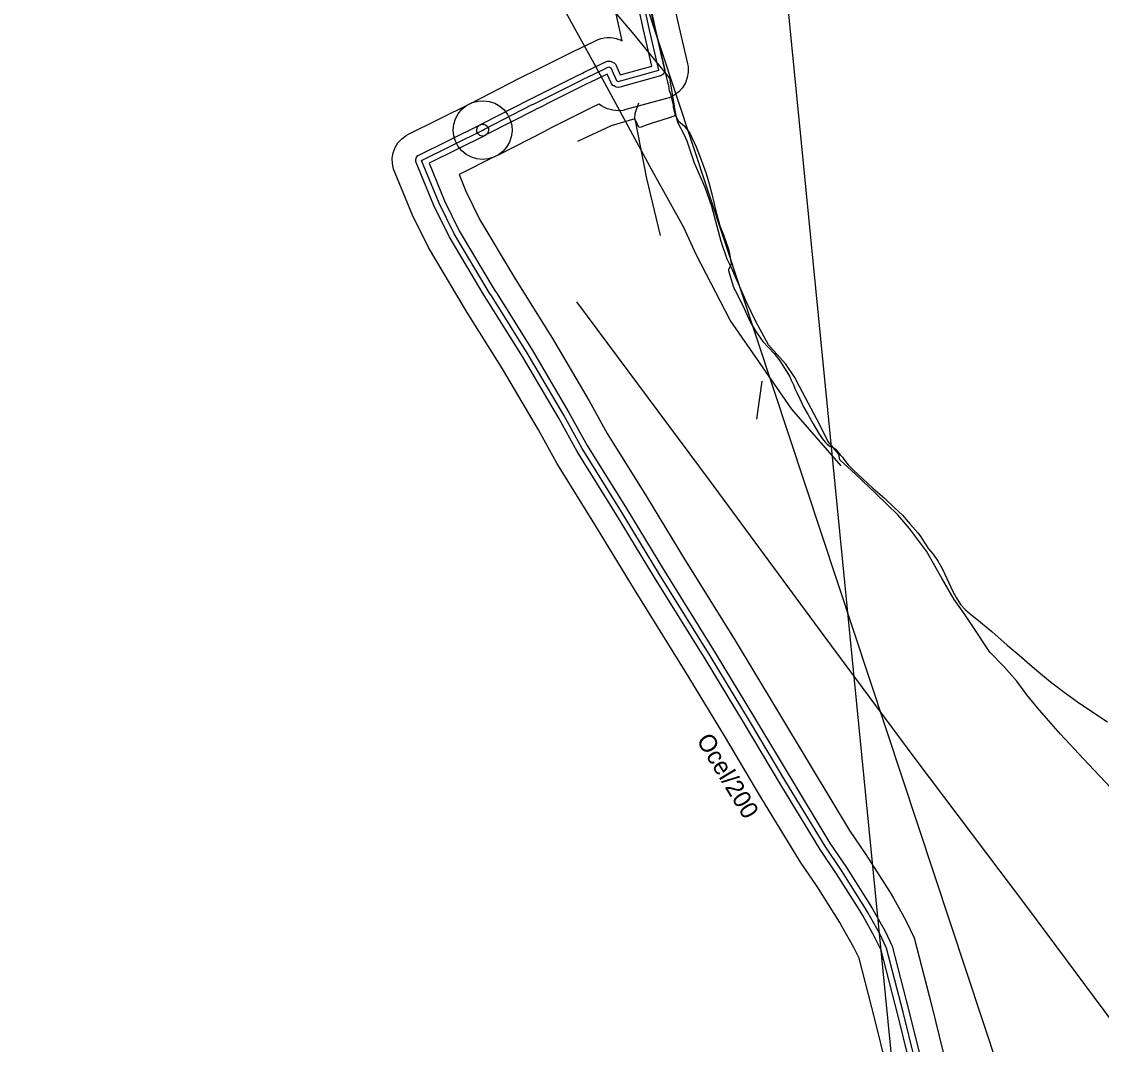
# Model space of a CAD drawing. Extents: x -555222 to -543220, y -1067119 to -1030889.
# Drawn here: x -550559 to -549821, y -1046964 to -1046265 of the extents above; entities that cross this region are included whole.
import ezdxf

# ---------------------------------------------------------------- set-up
doc = ezdxf.new("R2010")
doc.units = 0
for name, color, linetype in [('07_ELEKTRO', 7, 'Continuous'), ('07_KANALIZACE', 7, 'Continuous'), ('07_OCH_P A POPISY TI', 7, 'Continuous'), ('07_PLYNOVOD', 7, 'Continuous'), ('07_SDĚLOVACÍ', 7, 'Continuous')]:
    doc.layers.add(name, color=color, linetype=linetype)

msp = doc.modelspace()

# ---------------------------------------------------------------- linework, layer by layer
at = {"layer": '07_ELEKTRO'}
for p, q in [((-550088.84, -1046578.41), (-550179.46, -1046456.56)), ((-550053.06, -1046510.77), (-550056.73, -1046536.66)), ((-550010.41, -1046684.72), (-550088.84, -1046578.41)), ((-549948.06, -1046768.56), (-550010.41, -1046684.72)), ((-549871.17, -1046870.7), (-549948.06, -1046768.56)), ((-549805.69, -1046958.54), (-549871.17, -1046870.7))]:
    msp.add_line(p, q, dxfattribs=at)
at = {"layer": '07_KANALIZACE'}
msp.add_lwpolyline([(-549998.78, -1046568.66), (-550032.5, -1046529.85), (-550074.63, -1046469.01), (-550097.74, -1046424.54), (-550106.48, -1046405.31), (-550126.67, -1046369.27), (-550167.68, -1046293.63), (-550196.35, -1046241.61)], dxfattribs=at)
at = {"layer": '07_OCH_P A POPISY TI'}
for p, q in [((-550119.87, -1046221.9), (-550110.42, -1046265.31)), ((-550149.46, -1046274.05), (-550158.95, -1046230.46)), ((-550133.84, -1046270.55), (-550143.32, -1046227.04)), ((-550135.5, -1046225.32), (-550126.04, -1046268.81)), ((-550110.42, -1046265.31), (-550104.34, -1046291.76)), ((-550148.53, -1046278.08), (-550149.46, -1046274.05)), ((-550128.12, -1046295.44), (-550133.84, -1046270.55)), ((-550126.04, -1046268.81), (-550119.93, -1046295.34)), ((-550181.46, -1046285.24), (-550168.56, -1046279.02)), ((-550168.56, -1046279.02), (-550168.04, -1046278.78)), ((-550168.04, -1046278.78), (-550167.63, -1046278.58)), ((-550167.63, -1046278.58), (-550165.79, -1046277.75)), ((-550165.79, -1046277.75), (-550164.85, -1046277.32)), ((-550164.85, -1046277.32), (-550162.88, -1046276.67)), ((-550162.88, -1046276.67), (-550160.86, -1046276.22)), ((-550160.86, -1046276.22), (-550158.8, -1046275.98)), ((-550158.8, -1046275.98), (-550156.72, -1046275.96)), ((-550156.72, -1046275.96), (-550154.66, -1046276.15)), ((-550154.66, -1046276.15), (-550152.62, -1046276.56)), ((-550152.62, -1046276.56), (-550150.64, -1046277.17)), ((-550150.64, -1046277.17), (-550149.69, -1046277.58)), ((-550149.69, -1046277.58), (-550148.53, -1046278.08)), ((-550207.45, -1046298.22), (-550186.93, -1046287.96)), ((-550186.93, -1046287.96), (-550182.74, -1046285.88)), ((-550182.74, -1046285.88), (-550181.46, -1046285.24)), ((-550174.42, -1046299.61), (-550161.61, -1046293.43)), ((-550161.61, -1046293.43), (-550161.14, -1046293.21)), ((-550161.14, -1046293.21), (-550160.91, -1046293.1)), ((-550160.91, -1046293.1), (-550159.2, -1046292.33)), ((-550159.2, -1046292.33), (-550158.43, -1046291.98)), ((-550158.43, -1046291.98), (-550156.75, -1046291.96)), ((-550156.75, -1046291.96), (-550155.98, -1046292.29)), ((-550155.98, -1046292.29), (-550154.6, -1046292.88)), ((-550154.6, -1046292.88), (-550153.89, -1046293.18)), ((-550153.89, -1046293.18), (-550152.8, -1046294.27)), ((-550152.8, -1046294.27), (-550152.5, -1046294.98)), ((-550152.5, -1046294.98), (-550149.74, -1046301.36)), ((-550149.74, -1046301.36), (-550128.12, -1046295.44)), ((-550119.93, -1046295.34), (-550119.46, -1046297.4)), ((-550119.46, -1046297.4), (-550119.29, -1046298.15)), ((-550104.34, -1046291.76), (-550103.87, -1046293.82)), ((-550103.87, -1046293.82), (-550103.44, -1046295.69)), ((-550103.44, -1046295.69), (-550103.31, -1046299.52)), ((-550251.73, -1046320.74), (-550218.98, -1046303.99)), ((-550218.98, -1046303.99), (-550218.56, -1046303.77)), ((-550218.56, -1046303.77), (-550213.97, -1046301.48)), ((-550213.97, -1046301.48), (-550210.25, -1046299.62)), ((-550210.25, -1046299.62), (-550207.45, -1046298.22)), ((-550200.3, -1046312.53), (-550179.79, -1046302.28)), ((-550179.79, -1046302.28), (-550175.61, -1046300.2)), ((-550175.61, -1046300.2), (-550174.42, -1046299.61)), ((-550158.66, -1046300.89), (-550170.9, -1046306.79)), ((-550156.06, -1046306.91), (-550158.66, -1046300.89)), ((-550122.3, -1046302.15), (-550150.14, -1046309.77)), ((-550121.56, -1046301.94), (-550122.3, -1046302.15)), ((-550120.32, -1046301.01), (-550121.56, -1046301.94)), ((-550119.53, -1046299.68), (-550120.32, -1046301.01)), ((-550119.29, -1046298.15), (-550119.53, -1046299.68)), ((-550103.9, -1046303.31), (-550105.21, -1046306.91)), ((-550103.31, -1046299.52), (-550103.9, -1046303.31)), ((-550176.21, -1046309.44), (-550196.72, -1046319.69)), ((-550172.04, -1046307.36), (-550176.21, -1046309.44)), ((-550170.9, -1046306.79), (-550172.04, -1046307.36)), ((-550155.78, -1046307.58), (-550156.06, -1046306.91)), ((-550154.77, -1046308.63), (-550155.78, -1046307.58)), ((-550154.11, -1046308.94), (-550154.77, -1046308.63)), ((-550153.92, -1046309.03), (-550154.11, -1046308.94)), ((-550152.96, -1046309.5), (-550153.92, -1046309.03)), ((-550152.3, -1046309.82), (-550152.96, -1046309.5)), ((-550150.85, -1046309.96), (-550152.3, -1046309.82)), ((-550150.14, -1046309.77), (-550150.85, -1046309.96)), ((-550107.18, -1046310.2), (-550109.74, -1046313.06)), ((-550105.21, -1046306.91), (-550107.18, -1046310.2)), ((-550250.9, -1046320.37), (-550247.1, -1046319.35)), ((-550247.1, -1046319.35), (-550243.16, -1046319.08)), ((-550244.34, -1046334.93), (-550211.68, -1046318.22)), ((-550243.16, -1046319.08), (-550239.26, -1046319.59)), ((-550239.26, -1046319.59), (-550235.52, -1046320.85)), ((-550211.68, -1046318.22), (-550211.33, -1046318.04)), ((-550211.33, -1046318.04), (-550206.82, -1046315.79)), ((-550206.82, -1046315.79), (-550203.1, -1046313.93)), ((-550203.1, -1046313.93), (-550200.3, -1046312.53)), ((-550118.08, -1046317.58), (-550145.92, -1046325.2)), ((-550116.23, -1046317.07), (-550118.08, -1046317.58)), ((-550112.79, -1046315.38), (-550116.23, -1046317.07)), ((-550109.74, -1046313.06), (-550112.79, -1046315.38)), ((-550294.45, -1046341.94), (-550252.66, -1046321.25)), ((-550260.47, -1046327.96), (-550257.96, -1046324.92)), ((-550257.96, -1046324.92), (-550254.91, -1046322.43)), ((-550254.91, -1046322.43), (-550253.17, -1046321.5)), ((-550253.17, -1046321.5), (-550251.73, -1046320.74)), ((-550252.66, -1046321.25), (-550250.9, -1046320.37)), ((-550208.02, -1046325.34), (-550240.64, -1046342.03)), ((-550235.52, -1046320.85), (-550232.11, -1046322.82)), ((-550232.11, -1046322.82), (-550229.14, -1046325.41)), ((-550229.14, -1046325.41), (-550226.74, -1046328.53)), ((-550207.71, -1046325.18), (-550208.02, -1046325.34)), ((-550203.24, -1046322.95), (-550207.71, -1046325.18)), ((-550199.52, -1046321.09), (-550203.24, -1046322.95)), ((-550196.72, -1046319.69), (-550199.52, -1046321.09)), ((-550169.07, -1046323.76), (-550189.57, -1046334)), ((-550164.91, -1046321.68), (-550169.07, -1046323.76)), ((-550164.32, -1046321.39), (-550164.91, -1046321.68)), ((-550162.62, -1046322.61), (-550164.32, -1046321.39)), ((-550160.99, -1046323.39), (-550162.62, -1046322.61)), ((-550160.88, -1046323.44), (-550160.99, -1046323.39)), ((-550160, -1046323.87), (-550160.88, -1046323.44)), ((-550158.37, -1046324.67), (-550160, -1046323.87)), ((-550154.88, -1046325.65), (-550158.37, -1046324.67)), ((-550151.28, -1046325.99), (-550154.88, -1046325.65)), ((-550147.67, -1046325.68), (-550151.28, -1046325.99)), ((-550145.92, -1046325.2), (-550147.67, -1046325.68)), ((-550263.49, -1046335.19), (-550262.33, -1046331.42)), ((-550262.33, -1046331.42), (-550260.47, -1046327.96)), ((-550226.74, -1046328.53), (-550225.87, -1046330.3)), ((-550225.87, -1046330.3), (-550224.99, -1046332.06)), ((-550224.99, -1046332.06), (-550223.97, -1046335.86)), ((-550189.57, -1046334), (-550192.37, -1046335.4)), ((-550287.36, -1046356.28), (-550245.56, -1046335.58)), ((-550263.89, -1046339.11), (-550263.49, -1046335.19)), ((-550263.51, -1046343.03), (-550263.89, -1046339.11)), ((-550247.85, -1046338.76), (-550247.38, -1046337.24)), ((-550247.7, -1046340.34), (-550247.85, -1046338.76)), ((-550247.32, -1046341.04), (-550247.7, -1046340.34)), ((-550247.38, -1046337.24), (-550246.37, -1046336.01)), ((-550246.95, -1046341.75), (-550247.32, -1046341.04)), ((-550246.37, -1046336.01), (-550245.66, -1046335.64)), ((-550245.66, -1046335.64), (-550244.34, -1046334.93)), ((-550245.56, -1046335.58), (-550244.85, -1046335.23)), ((-550244.85, -1046335.23), (-550243.26, -1046335.13)), ((-550243.26, -1046335.13), (-550241.76, -1046335.64)), ((-550241.76, -1046335.64), (-550240.56, -1046336.68)), ((-550240.26, -1046341.2), (-550241.3, -1046342.4)), ((-550240.56, -1046336.68), (-550240.2, -1046337.4)), ((-550239.75, -1046339.7), (-550240.26, -1046341.2)), ((-550240.2, -1046337.4), (-550239.85, -1046338.11)), ((-550239.85, -1046338.11), (-550239.75, -1046339.7)), ((-550200.72, -1046339.57), (-550233.25, -1046356.22)), ((-550223.7, -1046339.8), (-550224.21, -1046343.7)), ((-550223.97, -1046335.86), (-550223.7, -1046339.8)), ((-550200.48, -1046339.45), (-550200.72, -1046339.57)), ((-550196.09, -1046337.26), (-550200.48, -1046339.45)), ((-550192.37, -1046335.4), (-550196.09, -1046337.26)), ((-550303.65, -1046351.08), (-550301.68, -1046347.85)), ((-550301.68, -1046347.85), (-550299.15, -1046345.05)), ((-550299.15, -1046345.05), (-550296.14, -1046342.77)), ((-550296.14, -1046342.77), (-550294.45, -1046341.94)), ((-550242.02, -1046342.76), (-550280.45, -1046361.78)), ((-550262.38, -1046346.81), (-550263.51, -1046343.03)), ((-550261.46, -1046348.55), (-550262.38, -1046346.81)), ((-550260.53, -1046350.29), (-550261.46, -1046348.55)), ((-550245.72, -1046342.76), (-550246.95, -1046341.75)), ((-550244.2, -1046343.23), (-550245.72, -1046342.76)), ((-550242.62, -1046343.08), (-550244.2, -1046343.23)), ((-550241.92, -1046342.7), (-550242.62, -1046343.08)), ((-550241.3, -1046342.4), (-550242.02, -1046342.76)), ((-550240.64, -1046342.03), (-550241.92, -1046342.7)), ((-550225.47, -1046347.44), (-550227.44, -1046350.85)), ((-550224.21, -1046343.7), (-550225.47, -1046347.44)), ((-550305.61, -1046358.33), (-550304.97, -1046354.61)), ((-550304.97, -1046354.61), (-550303.65, -1046351.08)), ((-550288.04, -1046356.61), (-550287.36, -1046356.28)), ((-550258.04, -1046353.34), (-550260.53, -1046350.29)), ((-550255, -1046355.85), (-550258.04, -1046353.34)), ((-550251.54, -1046357.71), (-550255, -1046355.85)), ((-550233.15, -1046356.22), (-550234.92, -1046357.09)), ((-550233.25, -1046356.22), (-550234.41, -1046356.84)), ((-550230.03, -1046353.82), (-550233.15, -1046356.22)), ((-550227.44, -1046350.85), (-550230.03, -1046353.82)), ((-550305.54, -1046362.1), (-550305.61, -1046358.33)), ((-550304.77, -1046365.8), (-550305.54, -1046362.1)), ((-550289.59, -1046359.17), (-550289.06, -1046357.74)), ((-550289.57, -1046360.69), (-550289.59, -1046359.17)), ((-550289.27, -1046361.4), (-550289.57, -1046360.69)), ((-550277.08, -1046390.72), (-550289.27, -1046361.4)), ((-550289.06, -1046357.74), (-550288.04, -1046356.61)), ((-550280.45, -1046361.78), (-550269.78, -1046387.44)), ((-550234.92, -1046357.09), (-550259.92, -1046369.47)), ((-550247.77, -1046358.87), (-550251.54, -1046357.71)), ((-550243.85, -1046359.27), (-550247.77, -1046358.87)), ((-550239.93, -1046358.89), (-550243.85, -1046359.27)), ((-550236.15, -1046357.76), (-550239.93, -1046358.89)), ((-550234.41, -1046356.84), (-550236.15, -1046357.76)), ((-550304.05, -1046367.54), (-550304.77, -1046365.8)), ((-550291.67, -1046397.3), (-550304.05, -1046367.54)), ((-550259.92, -1046369.47), (-550255.19, -1046380.86)), ((-550255.19, -1046380.86), (-550245.66, -1046400.44)), ((-550266.79, -1046411.86), (-550277.08, -1046390.72)), ((-550269.78, -1046387.44), (-550259.75, -1046408.06)), ((-550280.88, -1046419.48), (-550291.67, -1046397.3)), ((-550245.66, -1046400.44), (-550222.21, -1046439.7)), ((-550259.75, -1046408.06), (-550235.88, -1046448.01)), ((-550242.72, -1046452.17), (-550266.79, -1046411.86)), ((-550256.39, -1046460.48), (-550280.88, -1046419.48)), ((-550222.21, -1046439.7), (-550220.4, -1046442.63)), ((-550220.4, -1046442.63), (-550196.11, -1046481.53)), ((-550240.79, -1046455.29), (-550242.72, -1046452.17)), ((-550235.88, -1046448.01), (-550233.99, -1046451.07)), ((-550233.99, -1046451.07), (-550209.79, -1046489.84)), ((-550216.63, -1046493.98), (-550240.79, -1046455.29)), ((-550254.38, -1046463.73), (-550256.39, -1046460.48)), ((-550230.31, -1046502.29), (-550254.38, -1046463.73)), ((-550196.11, -1046481.53), (-550170.98, -1046524.17)), ((-550191.82, -1046536.06), (-550216.63, -1046493.98)), ((-550209.79, -1046489.84), (-550184.88, -1046532.1)), ((-550205.72, -1046543.99), (-550230.31, -1046502.29)), ((-550170.98, -1046524.17), (-550158.6, -1046546.62)), ((-550184.88, -1046532.1), (-550172.4, -1046554.72)), ((-550179.3, -1046558.78), (-550191.82, -1046536.06)), ((-550193.1, -1046566.88), (-550205.72, -1046543.99)), ((-550158.6, -1046546.62), (-550131.87, -1046589.45)), ((-550172.4, -1046554.72), (-550145.5, -1046597.84)), ((-550152.32, -1046602.02), (-550179.3, -1046558.78)), ((-550165.95, -1046610.41), (-550193.1, -1046566.88)), ((-550131.87, -1046589.45), (-550105.91, -1046632.3)), ((-550145.5, -1046597.84), (-550119.55, -1046640.67)), ((-550126.37, -1046644.85), (-550152.32, -1046602.02)), ((-550140.01, -1046653.22), (-550165.95, -1046610.41)), ((-550105.91, -1046632.3), (-550071.29, -1046687.99)), ((-550119.55, -1046640.67), (-550084.92, -1046696.37)), ((-550091.74, -1046700.55), (-550126.37, -1046644.85)), ((-550105.37, -1046708.93), (-550140.01, -1046653.22)), ((-550071.29, -1046687.99), (-550044.23, -1046732.6)), ((-550064.8, -1046744.97), (-550091.74, -1046700.55)), ((-550084.92, -1046696.37), (-550057.94, -1046740.85)), ((-550078.51, -1046753.22), (-550105.37, -1046708.93)), ((-550044.23, -1046732.6), (-550019.32, -1046774.31)), ((-550039.89, -1046786.68), (-550064.8, -1046744.97)), ((-550057.94, -1046740.85), (-550033.03, -1046782.56)), ((-550053.6, -1046794.93), (-550078.51, -1046753.22)), ((-550019.32, -1046774.31), (-549992.94, -1046817.8)), ((-550033.03, -1046782.56), (-550006.4, -1046826.46)), ((-550013.14, -1046830.78), (-550039.89, -1046786.68)), ((-550026.6, -1046839.44), (-550053.6, -1046794.93)), ((-549992.94, -1046817.8), (-549981.79, -1046834.18)), ((-550006.4, -1046826.46), (-549995.16, -1046842.98)), ((-550001.84, -1046847.38), (-550013.14, -1046830.78)), ((-549981.79, -1046834.18), (-549965.29, -1046860.11)), ((-550015.21, -1046856.18), (-550026.6, -1046839.44)), ((-549995.16, -1046842.98), (-549979.04, -1046868.31)), ((-549985.92, -1046872.41), (-550001.84, -1046847.38)), ((-549999.67, -1046880.61), (-550015.21, -1046856.18)), ((-549965.29, -1046860.11), (-549963.08, -1046864.09)), ((-549963.08, -1046864.09), (-549954.58, -1046879.28)), ((-549984.03, -1046875.79), (-549985.92, -1046872.41)), ((-549979.04, -1046868.31), (-549977.05, -1046871.89)), ((-549977.05, -1046871.89), (-549968.78, -1046886.66)), ((-549975.88, -1046890.36), (-549984.03, -1046875.79)), ((-549954.58, -1046879.28), (-549948.82, -1046891.25)), ((-549998, -1046883.59), (-549999.67, -1046880.61)), ((-549990.08, -1046897.74), (-549998, -1046883.59)), ((-549968.78, -1046886.66), (-549963.91, -1046896.79)), ((-549971.45, -1046899.55), (-549975.88, -1046890.36)), ((-549948.82, -1046891.25), (-549936.9, -1046937.01)), ((-549986.54, -1046905.09), (-549990.08, -1046897.74)), ((-549960.17, -1046942.89), (-549971.45, -1046899.55)), ((-549963.91, -1046896.79), (-549952.41, -1046940.93)), ((-549975.68, -1046946.81), (-549986.54, -1046905.09)), ((-549936.9, -1046937.01), (-549928.95, -1046969.41)), ((-549967.77, -1046979.03), (-549975.68, -1046946.81)), ((-549952.24, -1046975.18), (-549960.17, -1046942.89)), ((-549952.41, -1046940.93), (-549944.48, -1046973.26))]:
    msp.add_line(p, q, dxfattribs=at)
at = {"layer": '07_PLYNOVOD'}
for points in [[(-550243.79, -1046339.17), (-550242.49, -1046338.48), (-550209.85, -1046321.78), (-550209.52, -1046321.61), (-550205.03, -1046319.37), (-550201.31, -1046317.51), (-550198.51, -1046316.11), (-550178, -1046305.86), (-550173.83, -1046303.78), (-550172.66, -1046303.2), (-550159.87, -1046297.04), (-550159.42, -1046296.82), (-550159.23, -1046296.73), (-550157.55, -1046295.97), (-550156.17, -1046296.56), (-550152.39, -1046305.33), (-550152.18, -1046305.43), (-550151.2, -1046305.91), (-550123.36, -1046298.29), (-550123.83, -1046296.24), (-550129.94, -1046269.68), (-550139.41, -1046226.18)], [(-549948.36, -1046974.22), (-549956.29, -1046941.91), (-549967.68, -1046898.17), (-549972.33, -1046888.51), (-549980.54, -1046873.84), (-549982.48, -1046870.36), (-549998.5, -1046845.18), (-550009.77, -1046828.62), (-550036.46, -1046784.62), (-550061.37, -1046742.91), (-550088.33, -1046698.46), (-550122.96, -1046642.76), (-550148.91, -1046599.93), (-550175.85, -1046556.75), (-550188.35, -1046534.08), (-550213.21, -1046491.91), (-550237.39, -1046453.18), (-550239.3, -1046450.09), (-550263.27, -1046409.96), (-550273.43, -1046389.08), (-550285.58, -1046359.86), (-550243.79, -1046339.17)]]:
    msp.add_lwpolyline(points, dxfattribs=at)
at = {"layer": '07_SDĚLOVACÍ'}
for p, q in [((-555221.67, -1030889), (-543220.07, -1067118.92)), ((-550531.78, -1041228.78), (-549789.42, -1048745))]:
    msp.add_line(p, q, dxfattribs=at)
for points in [[(-550111.94, -1046329.19), (-550112.21, -1046328.35), (-550113.26, -1046323.48), (-550113.32, -1046322.07), (-550114.16, -1046318.35), (-550114.88, -1046315.32), (-550116.03, -1046312.35), (-550116.52, -1046309.01), (-550117.25, -1046306.36), (-550118.29, -1046301.64), (-550119.68, -1046296.19), (-550121.59, -1046288.26), (-550124.46, -1046275.05), (-550127.43, -1046263.38), (-550131.17, -1046246.31), (-550134.11, -1046232.23), (-550137.39, -1046217.15)], [(-550140.33, -1046273.81), (-550156.85, -1046254.35), (-550164.57, -1046241.91)], [(-550112.72, -1046323.26), (-550112.66, -1046322.5), (-550115.92, -1046303.73), (-550140.33, -1046273.81)], [(-550139.72, -1046331.5), (-550139.6, -1046327.9), (-550137.01, -1046320.63)], [(-550113.26, -1046323.48), (-550112.21, -1046328.35)], [(-550076.77, -1046427.47), (-550080.67, -1046415.23), (-550087.12, -1046391.48), (-550091.65, -1046378.34), (-550098.89, -1046361.76), (-550104.07, -1046346.84), (-550105.98, -1046342.18), (-550110.32, -1046334.03), (-550111.8, -1046327.96), (-550112.72, -1046323.26)], [(-550139.72, -1046331.5), (-550155.91, -1046336.15), (-550178.94, -1046346.87)], [(-550111.94, -1046329.19), (-550115.63, -1046330.57), (-550122.08, -1046332.61), (-550127.21, -1046334.12), (-550132.08, -1046335.83), (-550136.15, -1046337.31), (-550136.73, -1046337.09), (-550137.47, -1046336.39), (-550139.46, -1046332.27), (-550139.72, -1046331.5)], [(-550139.72, -1046331.5), (-550131.7, -1046372.17), (-550122.43, -1046411.15)], [(-550139.46, -1046332.27), (-550137.47, -1046336.39)], [(-550111.94, -1046329.19), (-550111.68, -1046329.91)], [(-550111.68, -1046329.91), (-550111.51, -1046330.39)], [(-550111.51, -1046330.39), (-550111.38, -1046330.74), (-550110.91, -1046331.45), (-550109.88, -1046333.08), (-550108.83, -1046334.08), (-550105.95, -1046336.31), (-550102.29, -1046341.34), (-550097.78, -1046350.63), (-550094.44, -1046359.39), (-550091.09, -1046368.83), (-550088.96, -1046375.79), (-550086.94, -1046383.69), (-550084.73, -1046393.6), (-550081.57, -1046404.52), (-550079.19, -1046410.83), (-550075.85, -1046420.44), (-550075, -1046423.54), (-550073.86, -1046430.62), (-550073.98, -1046431.06), (-550075.71, -1046434.34), (-550075.83, -1046435.14), (-550074.72, -1046438.99), (-550072.54, -1046445.81), (-550071.57, -1046448.07)], [(-549951.94, -1046611.37), (-549960.04, -1046602.12), (-549974.59, -1046588.02), (-549989.04, -1046574.39), (-549999.6, -1046564.56), (-550000.26, -1046560.62), (-550007.75, -1046551.86), (-550013.2, -1046540.98), (-550027.13, -1046514.5), (-550030.45, -1046508.15), (-550036.52, -1046499.1), (-550045.1, -1046489.8), (-550048.48, -1046485.83), (-550057.03, -1046469.88), (-550063.22, -1046457.19), (-550073.63, -1046433.34), (-550076.77, -1046427.47)], [(-550071.57, -1046448.07), (-550071.13, -1046448.87), (-550066.05, -1046459.13), (-550061.04, -1046470.09)], [(-550061.04, -1046470.09), (-550059.43, -1046473.04), (-550057.05, -1046476.74), (-550052.2, -1046483.65), (-550044.59, -1046491.74), (-550040.56, -1046496.92), (-550035.79, -1046504.32), (-550033.97, -1046507.44), (-550032.83, -1046510.05), (-550031.19, -1046513.74)], [(-550035.79, -1046504.32), (-550033.97, -1046507.44), (-550032.83, -1046510.05), (-550031.19, -1046513.74), (-550030.32, -1046515.71)], [(-550031.19, -1046513.74), (-550030.32, -1046515.71), (-550029.11, -1046518.43), (-550027, -1046522.91), (-550024.24, -1046528.72), (-550021.38, -1046533.8), (-550017.97, -1046540), (-550014.07, -1046546.61), (-550011.66, -1046549.88), (-550009.59, -1046552.49), (-550008.38, -1046553.75), (-550006.46, -1046555.1), (-550004.95, -1046555.74), (-550003.54, -1046556.5), (-550002.67, -1046557.22), (-549999.37, -1046561.06), (-549997.83, -1046562.76), (-549995.89, -1046565.58), (-549993.96, -1046568.01), (-549990.29, -1046571.58), (-549983.84, -1046577.42)], [(-549983.84, -1046577.42), (-549977.02, -1046583.88), (-549969.2, -1046590.63), (-549962.5, -1046596.99), (-549956.78, -1046602.4), (-549951.67, -1046608.45), (-549946.36, -1046614.32), (-549944.86, -1046616.4), (-549941.96, -1046620.87), (-549939.07, -1046625.21), (-549935.81, -1046629.08), (-549932.34, -1046633.94), (-549929.66, -1046638.68), (-549926.53, -1046645.54), (-549922.43, -1046654.56), (-549920.18, -1046658.65), (-549917.23, -1046663.44), (-549913.66, -1046667), (-549910.66, -1046669.85), (-549903.42, -1046675.33), (-549895.72, -1046681.84), (-549885.22, -1046691.04), (-549877.15, -1046698.02), (-549869.77, -1046704.45), (-549862.25, -1046710.63), (-549854.64, -1046716.83), (-549846.36, -1046723.31), (-549837.27, -1046729.91), (-549825.33, -1046737.82), (-549816.68, -1046743.55)], [(-549811.03, -1046792.3), (-549833.1, -1046768.86), (-549848.72, -1046752.03), (-549858.37, -1046740.94), (-549864.43, -1046733.88), (-549871.78, -1046725.02), (-549878.66, -1046715.78), (-549887.26, -1046705.98), (-549897.13, -1046695.88), (-549908.75, -1046678.4), (-549914.63, -1046669.49), (-549921.45, -1046660.03), (-549929.62, -1046645.72), (-549940.38, -1046626.91), (-549951.94, -1046611.37)]]:
    msp.add_lwpolyline(points, dxfattribs=at)

# ---------------------------------------------------------------- texts
at = {"layer": '07_OCH_P A POPISY TI'}
msp.add_text('Ocel/200', height=12, rotation=301.23782, dxfattribs=at).set_placement((-550097.97, -1046756.02))

doc.saveas('drawing.dxf')
